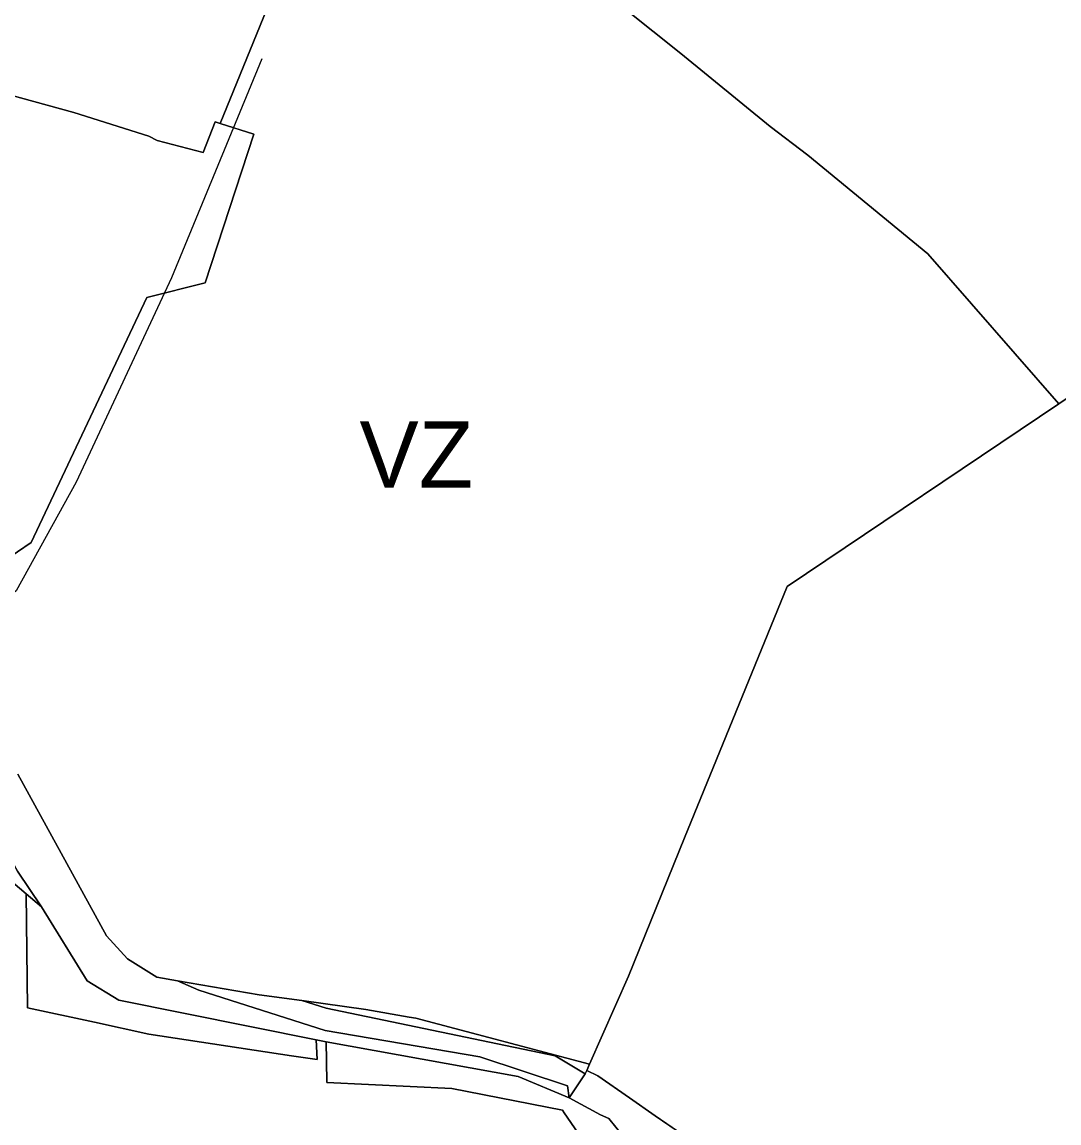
# Model space of a CAD drawing. Extents: x -555509 to -553005, y -1186756 to -1182560.
# Drawn here: x -554047.8 to -553829.3, y -1184544.3 to -1184312.3 of the extents above; entities that cross this region are included whole.
import ezdxf

# ---------------------------------------------------------------- set-up
doc = ezdxf.new("R2010")
doc.units = 0
for name, color, linetype in [('Level 15', 7, 'Continuous'), ('Level 26', 7, 'Continuous'), ('Level 31', 7, 'Continuous'), ('Level 36', 7, 'Continuous'), ('Level 52', 7, 'Continuous'), ('Level 59', 7, 'Continuous'), ('Level 6', 7, 'Continuous'), ('OBRYS_PLOCH', 7, 'Continuous'), ('stav_AP', 7, 'Continuous'), ('stav_AT', 7, 'Continuous'), ('stav_PU', 7, 'Continuous'), ('stav_VL', 7, 'Continuous'), ('stav_VZ', 7, 'Continuous'), ('stav_ZK', 7, 'Continuous'), ('stav_ZZ', 7, 'Continuous')]:
    doc.layers.add(name, color=color, linetype=linetype)

msp = doc.modelspace()

# ---------------------------------------------------------------- linework, layer by layer
at = {"layer": 'Level 15'}
for p, q in [((-554010.57, -1184516.33), (-554015.05, -1184514.32)), ((-553997.88, -1184517.25), (-554015.05, -1184514.32)), ((-554015.05, -1184514.32), (-554010.57, -1184516.33)), ((-553983.96, -1184524.79), (-554010.57, -1184516.33)), ((-554010.57, -1184516.33), (-553983.96, -1184524.79)), ((-553988.88, -1184518.51), (-553997.88, -1184517.25)), ((-553988.88, -1184518.51), (-553983.77, -1184520.06)), ((-553983.77, -1184520.06), (-553988.88, -1184518.51)), ((-553983.77, -1184520.06), (-553935.5, -1184530.13)), ((-553935.5, -1184530.13), (-553983.77, -1184520.06)), ((-553951.38, -1184530.35), (-553983.96, -1184524.79)), ((-553983.96, -1184524.79), (-553951.38, -1184530.35)), ((-553932.87, -1184536.43), (-553951.38, -1184530.35)), ((-553951.38, -1184530.35), (-553932.87, -1184536.43)), ((-553935.5, -1184530.13), (-553929.16, -1184533.92)), ((-553935.5, -1184530.13), (-553935.5, -1184530.13)), ((-553929.16, -1184533.92), (-553935.5, -1184530.13)), ((-553929.16, -1184533.92), (-553928.84, -1184533.21)), ((-553932.52, -1184538.98), (-553932.87, -1184536.43)), ((-553932.87, -1184536.43), (-553932.52, -1184538.98))]:
    msp.add_line(p, q, dxfattribs=at)
for points in [[(-554032.4, -1184500.51), (-554048.74, -1184470.8)], [(-554057.28, -1184475.96), (-554048.82, -1184491.25), (-554043.73, -1184498.74)], [(-554043.73, -1184498.74), (-554048.82, -1184491.25), (-554057.28, -1184475.96)], [(-554065.08, -1184480.67), (-554043.73, -1184498.74)], [(-554043.73, -1184498.74), (-554034.15, -1184514.33)], [(-554030.02, -1184504.83), (-554032.4, -1184500.51)], [(-554019.47, -1184513.57), (-554025.59, -1184509.67), (-554030.02, -1184504.83)], [(-554034.15, -1184514.33), (-554034.15, -1184514.33), (-554027.42, -1184518.38), (-553985.89, -1184526.77)], [(-554015.05, -1184514.32), (-554019.47, -1184513.57)], [(-553975.4, -1184520.39), (-553988.88, -1184518.51)], [(-553966.25, -1184521.97), (-553975.4, -1184520.39), (-553975.4, -1184520.39)], [(-553964.88, -1184522.21), (-553964.88, -1184522.21), (-553966.25, -1184521.97)], [(-553928.26, -1184531.89), (-553964.88, -1184522.21)], [(-553985.89, -1184526.77), (-553985.89, -1184526.77), (-553983.73, -1184527.21), (-553983.73, -1184527.21)], [(-553983.73, -1184527.21), (-553943.3, -1184534.51)], [(-553932.52, -1184538.98), (-553929.16, -1184533.92)], [(-553928.84, -1184533.21), (-553928.26, -1184531.89)], [(-553943.3, -1184534.51), (-553932.52, -1184538.98), (-553932.52, -1184538.98)]]:
    msp.add_lwpolyline(points, dxfattribs=at)
at = {"layer": 'Level 26'}
for p, q in [((-553929.16, -1184533.92), (-553932.52, -1184538.98)), ((-553928.84, -1184533.21), (-553929.16, -1184533.92)), ((-553914.41, -1184542.78), (-553919.83, -1184538.99)), ((-553881.11, -1184565.44), (-553914.41, -1184542.78))]:
    msp.add_line(p, q, dxfattribs=at)
for points in [[(-553919.83, -1184538.99), (-553926.52, -1184534.32), (-553928.84, -1184533.21)], [(-553932.52, -1184538.98), (-553925.92, -1184542.59), (-553924.15, -1184543.36)], [(-553924.15, -1184543.36), (-553921.25, -1184547.01), (-553920.61, -1184553.15), (-553919.86, -1184560.27), (-553918.79, -1184573.46)]]:
    msp.add_lwpolyline(points, dxfattribs=at)
at = {"layer": 'Level 31'}
msp.add_lwpolyline([(-553997.29, -1184320.09), (-554016.36, -1184366.23), (-554036.46, -1184409.26), (-554049.09, -1184432.2), (-554098.06, -1184473.18), (-554142.9, -1184516.99), (-554206.3, -1184543.54), (-554246.24, -1184609), (-554366.6, -1184711.57), (-554375.17, -1184735.92), (-554380.97, -1184742.11), (-554402.36, -1184756.03), (-554415.63, -1184766.72), (-554409.45, -1184838.88), (-554423.36, -1184867.62), (-554433.16, -1184895.06), (-554448.23, -1184939.39), (-554444.24, -1184998.93), (-554443.72, -1185035.39), (-554434.96, -1185098.79), (-554425.81, -1185158.84), (-554425.17, -1185178.04), (-554431.86, -1185204.97), (-554445.49, -1185223.21)], dxfattribs=at)
at = {"layer": 'Level 36'}
msp.add_line((-554055.96, -1184488.39), (-554043.73, -1184498.74), dxfattribs=at)
for points in [[(-553856.94, -1184361.2), (-553882.23, -1184340.38), (-553890.19, -1184334.36), (-553909.03, -1184319), (-553944.41, -1184290.7)], [(-553996.23, -1184309.64), (-554006.09, -1184333.7), (-554007.16, -1184333.36), (-554009.7, -1184339.84), (-554019.38, -1184337.28), (-554021.12, -1184336.41), (-554036.96, -1184331.42), (-554061.51, -1184324.7), (-554076.01, -1184320.94), (-554084.8, -1184318.51), (-554114.73, -1184311.21)], [(-553920.04, -1184513.36), (-553908.23, -1184484.2), (-553886.58, -1184431.24), (-553829.38, -1184392.78), (-553856.94, -1184361.2)], [(-554043.73, -1184498.74), (-554034.15, -1184514.33), (-554027.42, -1184518.38), (-553985.89, -1184526.77), (-553983.73, -1184527.21), (-553943.3, -1184534.51), (-553932.52, -1184538.98), (-553929.16, -1184533.92), (-553928.84, -1184533.21), (-553928.26, -1184531.89), (-553920.04, -1184513.36)]]:
    msp.add_lwpolyline(points, dxfattribs=at)
at = {"layer": 'Level 52'}
for points in [[(-553856.94, -1184361.2), (-553882.23, -1184340.38), (-553890.19, -1184334.36), (-553909.03, -1184319), (-553944.41, -1184290.7)], [(-553996.23, -1184309.64), (-554006.09, -1184333.7), (-554007.16, -1184333.36), (-554009.7, -1184339.84), (-554019.38, -1184337.28), (-554021.12, -1184336.41), (-554036.96, -1184331.42), (-554061.51, -1184324.7), (-554076.01, -1184320.94), (-554084.8, -1184318.51), (-554114.73, -1184311.21)], [(-553920.04, -1184513.36), (-553908.23, -1184484.2), (-553886.58, -1184431.24), (-553829.38, -1184392.78), (-553856.94, -1184361.2)], [(-554099.56, -1184448.52), (-554096.79, -1184449.95), (-554078.37, -1184459.39), (-554065.08, -1184480.67), (-554043.73, -1184498.74), (-554034.15, -1184514.33), (-554027.42, -1184518.38), (-553985.89, -1184526.77), (-553983.73, -1184527.21), (-553943.3, -1184534.51), (-553932.52, -1184538.98), (-553929.16, -1184533.92), (-553928.84, -1184533.21), (-553928.26, -1184531.89), (-553920.04, -1184513.36)]]:
    msp.add_lwpolyline(points, dxfattribs=at)
at = {"layer": 'Level 6'}
for points in [[(-553856.94, -1184361.2), (-553882.23, -1184340.38), (-553890.19, -1184334.36), (-553909.03, -1184319), (-553944.41, -1184290.7)], [(-553996.23, -1184309.64), (-554006.09, -1184333.7), (-554007.16, -1184333.36), (-554009.7, -1184339.84), (-554019.38, -1184337.28), (-554021.12, -1184336.41), (-554036.96, -1184331.42), (-554061.51, -1184324.7), (-554076.01, -1184320.94), (-554084.8, -1184318.51), (-554114.73, -1184311.21)], [(-553920.04, -1184513.36), (-553908.23, -1184484.2), (-553886.58, -1184431.24), (-553829.38, -1184392.78), (-553856.94, -1184361.2)], [(-554096.79, -1184449.95), (-554078.37, -1184459.39), (-554065.08, -1184480.67), (-554043.73, -1184498.74), (-554034.15, -1184514.33), (-554027.42, -1184518.38), (-553985.89, -1184526.77), (-553983.73, -1184527.21), (-553943.3, -1184534.51), (-553932.52, -1184538.98), (-553929.16, -1184533.92), (-553928.84, -1184533.21), (-553928.26, -1184531.89), (-553920.04, -1184513.36)]]:
    msp.add_lwpolyline(points, dxfattribs=at)
at = {"layer": 'OBRYS_PLOCH'}
for p, q in [((-553996.23, -1184309.64), (-554006.09, -1184333.7)), ((-553909.03, -1184319), (-553890.19, -1184334.36)), ((-553829.38, -1184392.78), (-553856.94, -1184361.2)), ((-553856.94, -1184361.2), (-553829.38, -1184392.78)), ((-554021.52, -1184370.38), (-554045.95, -1184421.98)), ((-554045.95, -1184421.98), (-554066.54, -1184436.07)), ((-554048.74, -1184470.8), (-554032.4, -1184500.51)), ((-554046.95, -1184496.01), (-554052.63, -1184491.21)), ((-554043.73, -1184498.74), (-554046.95, -1184496.01)), ((-554034.15, -1184514.33), (-554043.73, -1184498.74)), ((-554032.4, -1184500.51), (-554030.02, -1184504.83)), ((-554030.02, -1184504.83), (-554025.59, -1184509.67)), ((-554025.59, -1184509.67), (-554019.47, -1184513.57)), ((-554027.42, -1184518.38), (-554034.15, -1184514.33)), ((-554019.47, -1184513.57), (-554015.05, -1184514.32)), ((-554015.05, -1184514.32), (-553997.88, -1184517.25)), ((-553997.88, -1184517.25), (-553988.88, -1184518.51)), ((-553985.89, -1184526.77), (-554027.42, -1184518.38)), ((-553988.88, -1184518.51), (-553975.4, -1184520.39)), ((-553975.4, -1184520.39), (-553966.25, -1184521.97)), ((-553966.25, -1184521.97), (-553964.88, -1184522.21)), ((-553964.88, -1184522.21), (-553928.26, -1184531.89)), ((-553983.73, -1184527.21), (-553985.89, -1184526.77)), ((-553929.16, -1184533.92), (-553932.52, -1184538.98)), ((-553928.84, -1184533.21), (-553929.16, -1184533.92)), ((-553928.26, -1184531.89), (-553928.84, -1184533.21)), ((-553914.41, -1184542.78), (-553919.83, -1184538.99)), ((-553881.11, -1184565.44), (-553914.41, -1184542.78))]:
    msp.add_line(p, q, dxfattribs=at)
for points in [[(-553965.73, -1184273.58), (-553944.41, -1184290.7), (-553909.03, -1184319)], [(-553890.19, -1184334.36), (-553909.03, -1184319), (-553944.41, -1184290.7)], [(-554009.7, -1184339.84), (-554007.16, -1184333.36), (-554006.09, -1184333.7), (-553996.23, -1184309.64)], [(-554076.01, -1184320.94), (-554061.51, -1184324.7), (-554036.96, -1184331.42), (-554021.12, -1184336.41)], [(-554021.12, -1184336.41), (-554036.96, -1184331.42), (-554061.51, -1184324.7), (-554076.01, -1184320.94)], [(-554075.6, -1184440.19), (-554066.54, -1184436.07), (-554045.95, -1184421.98), (-554021.52, -1184370.38), (-554009.27, -1184367.29), (-553998.98, -1184335.94), (-554006.09, -1184333.7)], [(-554006.09, -1184333.7), (-553998.98, -1184335.94), (-554009.27, -1184367.29), (-554021.52, -1184370.38)], [(-554006.09, -1184333.7), (-554007.16, -1184333.36), (-554009.7, -1184339.84)], [(-553856.94, -1184361.2), (-553882.23, -1184340.38), (-553890.19, -1184334.36)], [(-553890.19, -1184334.36), (-553882.23, -1184340.38), (-553856.94, -1184361.2)], [(-554021.12, -1184336.41), (-554019.38, -1184337.28), (-554009.7, -1184339.84)], [(-554009.7, -1184339.84), (-554019.38, -1184337.28), (-554021.12, -1184336.41)], [(-553623.25, -1184425.04), (-553764.35, -1184361.11), (-553775.07, -1184356.26), (-553829.38, -1184392.78)], [(-553829.38, -1184392.78), (-553775.07, -1184356.26), (-553764.35, -1184361.11), (-553623.25, -1184425.04)], [(-553928.26, -1184531.89), (-553920.04, -1184513.36), (-553908.23, -1184484.2), (-553886.58, -1184431.24), (-553829.38, -1184392.78)], [(-553829.38, -1184392.78), (-553886.58, -1184431.24), (-553908.23, -1184484.2), (-553920.04, -1184513.36), (-553928.26, -1184531.89)], [(-554046.95, -1184496.01), (-554046.7, -1184520.01), (-554032.58, -1184523.07), (-554021.13, -1184525.55)], [(-554021.13, -1184525.55), (-554032.58, -1184523.07), (-554046.7, -1184520.01), (-554046.95, -1184496.01)], [(-554021.13, -1184525.55), (-553991.04, -1184530.13), (-553985.63, -1184530.91), (-553985.89, -1184526.77)], [(-553985.89, -1184526.77), (-553985.63, -1184530.91), (-553991.04, -1184530.13), (-554021.13, -1184525.55)], [(-553932.52, -1184538.98), (-553943.3, -1184534.51), (-553983.73, -1184527.21)], [(-553983.73, -1184527.21), (-553983.69, -1184531.19), (-553983.64, -1184535.76), (-553957.28, -1184537.01), (-553933.93, -1184541.57), (-553933.57, -1184542.11), (-553926.18, -1184552.98), (-553923.85, -1184556.42), (-553923.79, -1184560.15), (-553923.59, -1184573.42), (-553923.5, -1184579.36), (-553923.39, -1184586.58), (-553923.28, -1184593.78), (-553923.19, -1184600.13)], [(-553923.19, -1184600.13), (-553923.28, -1184593.78), (-553923.39, -1184586.58), (-553923.5, -1184579.36), (-553923.59, -1184573.42), (-553923.79, -1184560.15), (-553923.85, -1184556.42), (-553926.18, -1184552.98), (-553933.57, -1184542.11), (-553933.93, -1184541.57), (-553957.28, -1184537.01), (-553983.64, -1184535.76), (-553983.69, -1184531.19), (-553983.73, -1184527.21)], [(-553919.83, -1184538.99), (-553926.52, -1184534.32), (-553928.84, -1184533.21)], [(-553928.84, -1184533.21), (-553926.52, -1184534.32), (-553919.83, -1184538.99), (-553914.41, -1184542.78), (-553881.11, -1184565.44), (-553837.69, -1184598.76), (-553803.8, -1184622.03)], [(-553924.15, -1184543.36), (-553925.92, -1184542.59), (-553932.52, -1184538.98)], [(-553932.52, -1184538.98), (-553925.92, -1184542.59), (-553924.15, -1184543.36)], [(-553918.79, -1184573.46), (-553919.86, -1184560.27), (-553920.61, -1184553.15), (-553921.25, -1184547.01), (-553924.15, -1184543.36)], [(-553924.15, -1184543.36), (-553921.25, -1184547.01), (-553920.61, -1184553.15), (-553919.86, -1184560.27), (-553918.79, -1184573.46)]]:
    msp.add_lwpolyline(points, dxfattribs=at)
at = {"layer": 'stav_AP'}
for p, q in [((-553909.03, -1184319), (-553890.19, -1184334.36)), ((-553856.94, -1184361.2), (-553829.38, -1184392.78))]:
    msp.add_line(p, q, dxfattribs=at)
for points in [[(-553965.73, -1184273.58), (-553944.41, -1184290.7), (-553909.03, -1184319)], [(-553890.19, -1184334.36), (-553882.23, -1184340.38), (-553856.94, -1184361.2)], [(-553829.38, -1184392.78), (-553775.07, -1184356.26), (-553764.35, -1184361.11), (-553623.25, -1184425.04)]]:
    msp.add_lwpolyline(points, dxfattribs=at)
at = {"layer": 'stav_AT'}
for p, q in [((-554046.95, -1184496.01), (-554052.63, -1184491.21)), ((-553983.73, -1184527.21), (-553985.89, -1184526.77)), ((-553928.26, -1184531.89), (-553928.84, -1184533.21))]:
    msp.add_line(p, q, dxfattribs=at)
for points in [[(-553623.25, -1184425.04), (-553764.35, -1184361.11), (-553775.07, -1184356.26), (-553829.38, -1184392.78)], [(-553829.38, -1184392.78), (-553886.58, -1184431.24), (-553908.23, -1184484.2), (-553920.04, -1184513.36), (-553928.26, -1184531.89)], [(-554021.13, -1184525.55), (-554032.58, -1184523.07), (-554046.7, -1184520.01), (-554046.95, -1184496.01)], [(-553985.89, -1184526.77), (-553985.63, -1184530.91), (-553991.04, -1184530.13), (-554021.13, -1184525.55)], [(-553923.19, -1184600.13), (-553923.28, -1184593.78), (-553923.39, -1184586.58), (-553923.5, -1184579.36), (-553923.59, -1184573.42), (-553923.79, -1184560.15), (-553923.85, -1184556.42), (-553926.18, -1184552.98), (-553933.57, -1184542.11), (-553933.93, -1184541.57), (-553957.28, -1184537.01), (-553983.64, -1184535.76), (-553983.69, -1184531.19), (-553983.73, -1184527.21)], [(-553928.84, -1184533.21), (-553926.52, -1184534.32), (-553919.83, -1184538.99), (-553914.41, -1184542.78), (-553881.11, -1184565.44), (-553837.69, -1184598.76), (-553803.8, -1184622.03)]]:
    msp.add_lwpolyline(points, dxfattribs=at)
at = {"layer": 'stav_PU'}
for p, q in [((-554032.4, -1184500.51), (-554048.74, -1184470.8)), ((-554065.08, -1184480.67), (-554043.73, -1184498.74)), ((-554043.73, -1184498.74), (-554034.15, -1184514.33)), ((-554030.02, -1184504.83), (-554032.4, -1184500.51)), ((-554015.05, -1184514.32), (-554019.47, -1184513.57)), ((-553997.88, -1184517.25), (-554015.05, -1184514.32)), ((-553988.88, -1184518.51), (-553997.88, -1184517.25)), ((-553975.4, -1184520.39), (-553988.88, -1184518.51)), ((-553966.25, -1184521.97), (-553975.4, -1184520.39)), ((-553964.88, -1184522.21), (-553966.25, -1184521.97)), ((-553928.26, -1184531.89), (-553964.88, -1184522.21)), ((-553985.89, -1184526.77), (-553983.73, -1184527.21)), ((-553983.73, -1184527.21), (-553943.3, -1184534.51)), ((-553932.52, -1184538.98), (-553929.16, -1184533.92)), ((-553929.16, -1184533.92), (-553928.84, -1184533.21)), ((-553928.84, -1184533.21), (-553928.26, -1184531.89)), ((-553943.3, -1184534.51), (-553932.52, -1184538.98))]:
    msp.add_line(p, q, dxfattribs=at)
for points in [[(-554019.47, -1184513.57), (-554025.59, -1184509.67), (-554030.02, -1184504.83)], [(-554034.15, -1184514.33), (-554027.42, -1184518.38), (-553985.89, -1184526.77)]]:
    msp.add_lwpolyline(points, dxfattribs=at)
at = {"layer": 'stav_VL'}
for points in [[(-554021.12, -1184336.41), (-554036.96, -1184331.42), (-554061.51, -1184324.7), (-554076.01, -1184320.94)], [(-554075.6, -1184440.19), (-554066.54, -1184436.07), (-554045.95, -1184421.98), (-554021.52, -1184370.38), (-554009.27, -1184367.29), (-553998.98, -1184335.94), (-554006.09, -1184333.7)], [(-554006.09, -1184333.7), (-554007.16, -1184333.36), (-554009.7, -1184339.84)], [(-554009.7, -1184339.84), (-554019.38, -1184337.28), (-554021.12, -1184336.41)]]:
    msp.add_lwpolyline(points, dxfattribs=at)
at = {"layer": 'stav_VZ'}
for p, q in [((-553996.23, -1184309.64), (-554006.09, -1184333.7)), ((-553829.38, -1184392.78), (-553856.94, -1184361.2)), ((-554021.52, -1184370.38), (-554045.95, -1184421.98)), ((-554045.95, -1184421.98), (-554066.54, -1184436.07)), ((-554048.74, -1184470.8), (-554032.4, -1184500.51)), ((-554032.4, -1184500.51), (-554030.02, -1184504.83)), ((-554030.02, -1184504.83), (-554025.59, -1184509.67)), ((-554025.59, -1184509.67), (-554019.47, -1184513.57)), ((-554019.47, -1184513.57), (-554015.05, -1184514.32)), ((-554015.05, -1184514.32), (-553997.88, -1184517.25)), ((-553997.88, -1184517.25), (-553988.88, -1184518.51)), ((-553988.88, -1184518.51), (-553975.4, -1184520.39)), ((-553975.4, -1184520.39), (-553966.25, -1184521.97)), ((-553966.25, -1184521.97), (-553964.88, -1184522.21)), ((-553964.88, -1184522.21), (-553928.26, -1184531.89))]:
    msp.add_line(p, q, dxfattribs=at)
for points in [[(-553890.19, -1184334.36), (-553909.03, -1184319), (-553944.41, -1184290.7)], [(-554006.09, -1184333.7), (-553998.98, -1184335.94), (-554009.27, -1184367.29), (-554021.52, -1184370.38)], [(-553856.94, -1184361.2), (-553882.23, -1184340.38), (-553890.19, -1184334.36)], [(-553928.26, -1184531.89), (-553920.04, -1184513.36), (-553908.23, -1184484.2), (-553886.58, -1184431.24), (-553829.38, -1184392.78)]]:
    msp.add_lwpolyline(points, dxfattribs=at)
at = {"layer": 'stav_ZK'}
for p, q in [((-554043.73, -1184498.74), (-554046.95, -1184496.01)), ((-554034.15, -1184514.33), (-554043.73, -1184498.74)), ((-554027.42, -1184518.38), (-554034.15, -1184514.33)), ((-553985.89, -1184526.77), (-554027.42, -1184518.38))]:
    msp.add_line(p, q, dxfattribs=at)
for points in [[(-554046.95, -1184496.01), (-554046.7, -1184520.01), (-554032.58, -1184523.07), (-554021.13, -1184525.55)], [(-554021.13, -1184525.55), (-553991.04, -1184530.13), (-553985.63, -1184530.91), (-553985.89, -1184526.77)], [(-553932.52, -1184538.98), (-553943.3, -1184534.51), (-553983.73, -1184527.21)], [(-553983.73, -1184527.21), (-553983.69, -1184531.19), (-553983.64, -1184535.76), (-553957.28, -1184537.01), (-553933.93, -1184541.57), (-553933.57, -1184542.11), (-553926.18, -1184552.98), (-553923.85, -1184556.42), (-553923.79, -1184560.15), (-553923.59, -1184573.42), (-553923.5, -1184579.36), (-553923.39, -1184586.58), (-553923.28, -1184593.78), (-553923.19, -1184600.13)], [(-553924.15, -1184543.36), (-553925.92, -1184542.59), (-553932.52, -1184538.98)], [(-553918.79, -1184573.46), (-553919.86, -1184560.27), (-553920.61, -1184553.15), (-553921.25, -1184547.01), (-553924.15, -1184543.36)]]:
    msp.add_lwpolyline(points, dxfattribs=at)
at = {"layer": 'stav_ZZ'}
for points in [[(-554009.7, -1184339.84), (-554007.16, -1184333.36), (-554006.09, -1184333.7), (-553996.23, -1184309.64)], [(-554076.01, -1184320.94), (-554061.51, -1184324.7), (-554036.96, -1184331.42), (-554021.12, -1184336.41)], [(-554021.12, -1184336.41), (-554019.38, -1184337.28), (-554009.7, -1184339.84)]]:
    msp.add_lwpolyline(points, dxfattribs=at)

# ---------------------------------------------------------------- texts
at = {"layer": 'Level 59'}
msp.add_text('VZ', height=14, dxfattribs=at).set_placement((-553976.73, -1184410.47))

doc.saveas('drawing.dxf')
